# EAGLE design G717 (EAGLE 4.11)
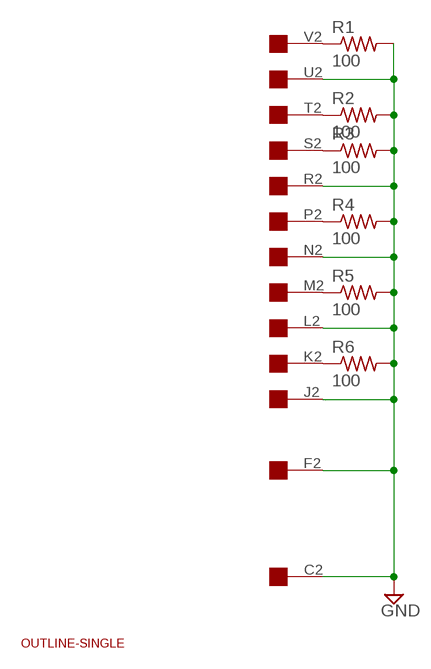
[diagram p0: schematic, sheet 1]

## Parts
R1  100  R-US_0207/10  [0207/10]
R2  100  R-US_0207/10  [0207/10]
R3  100  R-US_0207/10  [0207/10]
R4  100  R-US_0207/10  [0207/10]
R5  100  R-US_0207/10  [0207/10]
R6  100  R-US_0207/10  [0207/10]
U$1  OUTLINE-SINGLE  [SINGLE]
U$3  EDGE-1  [EDGE-CON1]

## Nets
GND [Supply]: R1.2 R2.2 R3.2 R4.2 R5.2 R6.2 U$3.C2 U$3.F2 U$3.J2 U$3.L2 U$3.N2 U$3.R2 U$3.U2
N$1: R1.1 U$3.V2
N$2: R2.1 U$3.T2
N$3: R3.1 U$3.S2
N$4: R4.1 U$3.P2
N$5: R5.1 U$3.M2
N$6: R6.1 U$3.K2
Unconnected: U$3.A2 U$3.B2 U$3.D2 U$3.E2 U$3.H2

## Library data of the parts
R1-R6 = rcl:R-US_: RESISTOR, American symbol
U$1 = dec-con:OUTLINE-*: Board outlines for DEC boards.
U$3 = dec-con:EDGE-1: Single-Sided DEC Edge Connector -- (side 2)

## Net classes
1 Supply: width 0.508 mm, drill 0.508 mm

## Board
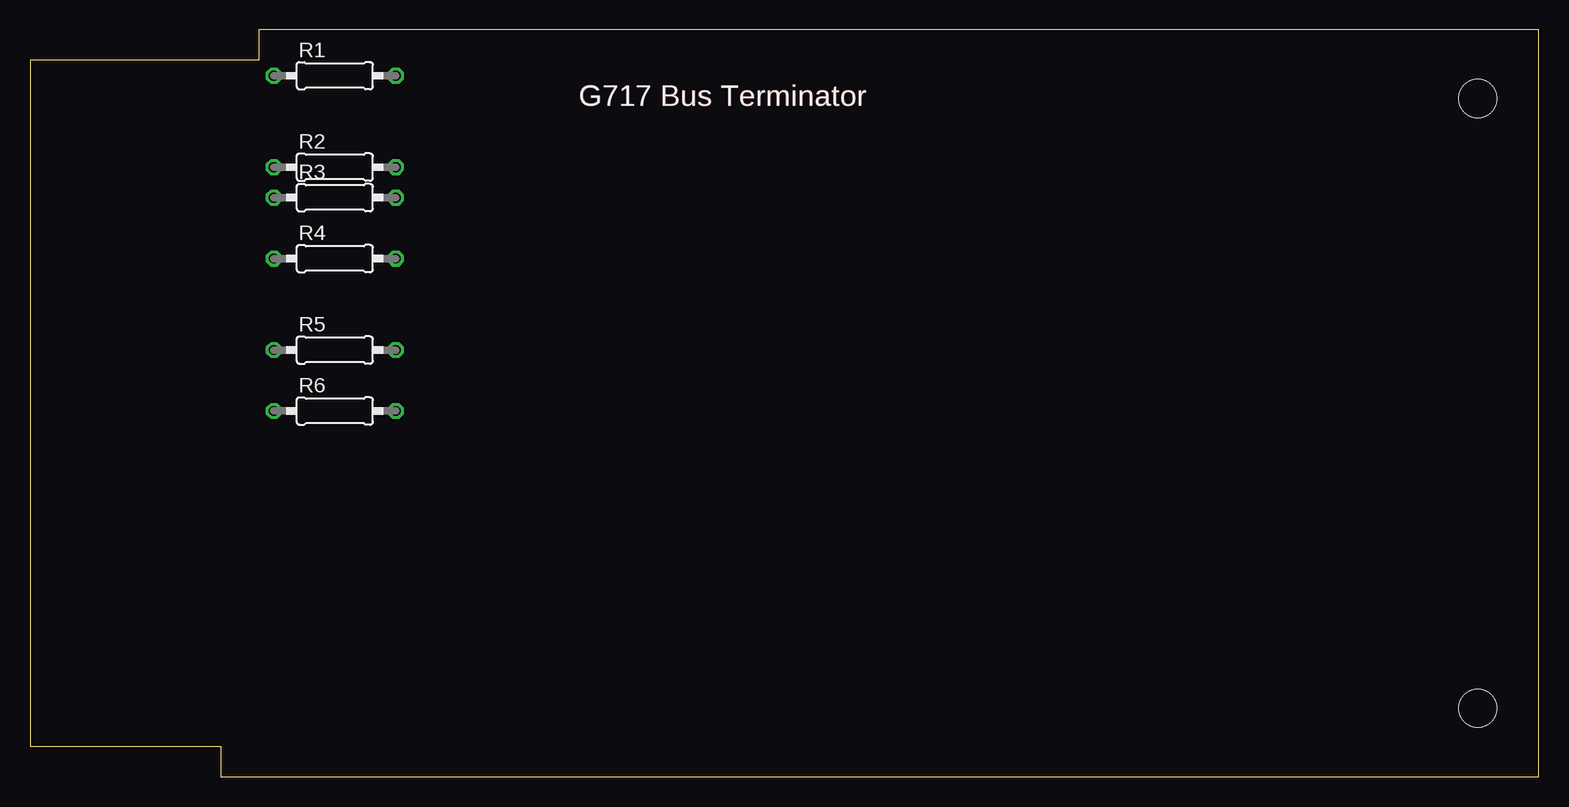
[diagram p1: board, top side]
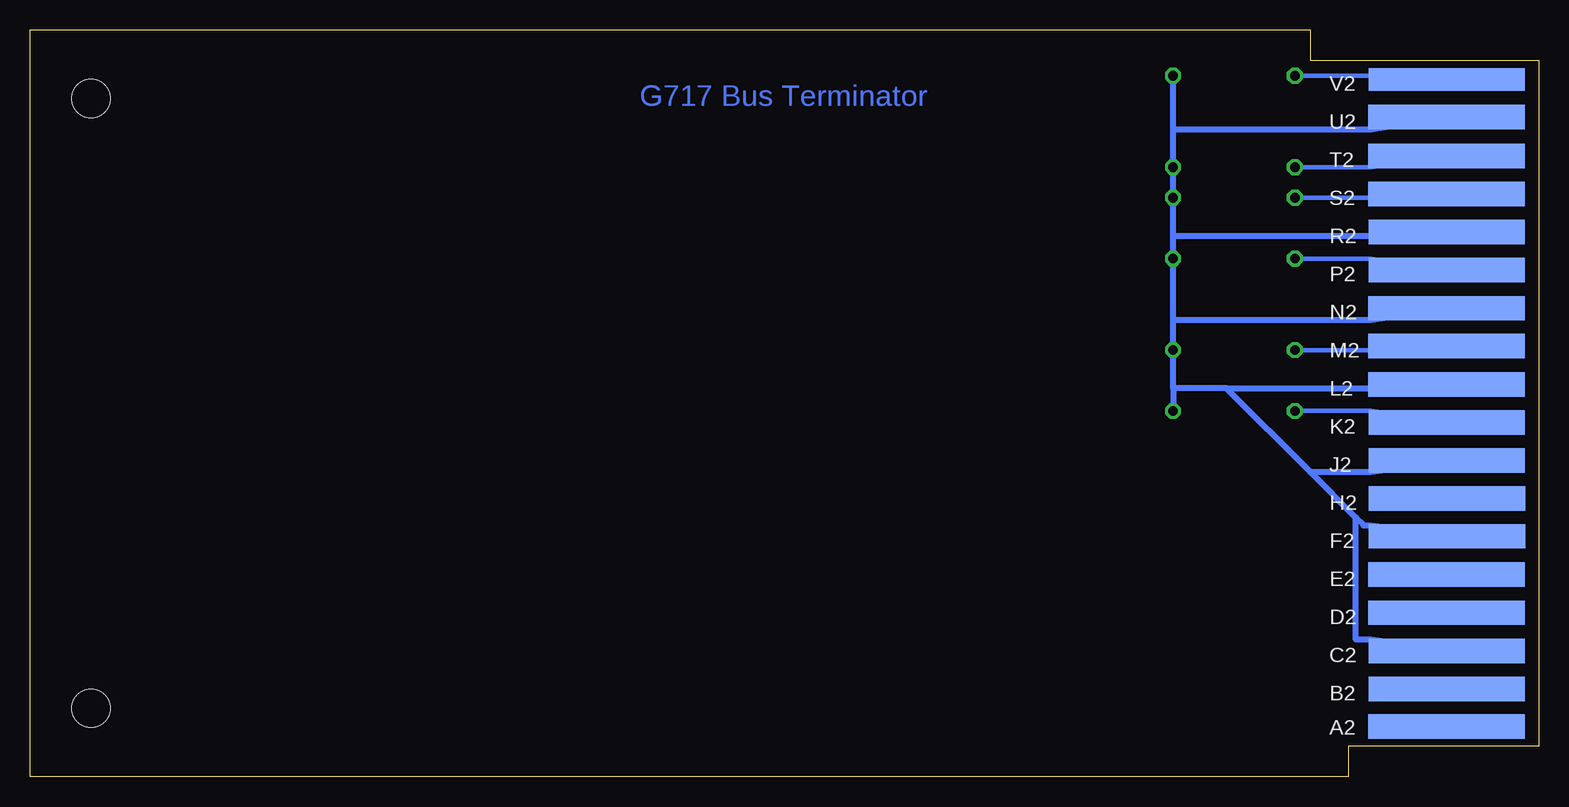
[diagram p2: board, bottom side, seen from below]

Size 125.73 x 62.23 mm. Coordinates in mm from the lower left corner, seen from the top.
Copper layers (1*16): Top 0.035mm / dielectric 1.5mm / Bottom 0.035mm
Design rules "15mils": minimum track width 15mil, minimum drill 24mil, track to track 15mil, track to pad 10mil, pad to pad 10mil, via to via 10mil, smd to smd 10mil, copper to edge 25mil, drill to drill 10mil, minimum pad ring 10mil, minimum via ring 8mil, stop-mask expansion 0mil, vias tented up to drill 0mil, thermal gap 10mil

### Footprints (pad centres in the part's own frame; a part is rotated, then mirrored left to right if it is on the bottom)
0207/10 = drill 0.813 octagon: 1 -5.08,0; 2 5.08,0
SINGLE = hole 3.175: 120.65,56.515; 120.65,5.715
EDGE-CON1 = smd 13.017 x 2.032 bottom: A2 7.69,4.194; B2 7.668,7.328; C2 7.668,10.49; D2 7.693,13.665; E2 7.693,16.84; F2 7.642,20.041; H2 7.642,23.19; J2 7.668,26.34; K2 7.668,29.515; L2 7.693,32.69; M2 7.693,35.89; N2 7.693,39.04; P2 7.668,42.24; R2 7.668,45.39; S2 7.693,48.565; T2 7.693,51.74; U2 7.693,54.966 | smd 13.017 x 1.905 bottom: V2 7.668,58.102

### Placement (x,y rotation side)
R1  25.4,58.42 0 top
R2  25.4,50.8 0 top
R3  25.4,48.26 0 top
R4  25.4,43.18 0 top
R5  25.4,35.56 0 top
R6  25.4,30.48 0 top
U$1  0,0 0 top
U$3  0,0 0 top

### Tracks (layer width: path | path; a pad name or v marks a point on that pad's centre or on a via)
GND
  Bottom 0.508: 30.48,32.38 30.48,34.92 R5.2 30.48,36.2 30.48,38.1 | 30.48,32.38 30.48,31.11 R6.2 | 30.48,45.09 30.48,47.62 R3.2 30.48,48.9 30.48,50.16 R2.2 30.48,51.44 30.48,53.98 | 30.48,45.09 30.48,43.81 R4.2 30.48,42.55 30.48,38.1 | 30.48,53.98 30.48,57.78 R1.2 | 26.04,32.38 13.97,32.38 U$3.L2 | 26.04,32.38 30.48,32.38 | 19.05,25.4 26.04,32.38 | 15.24,21.59 19.05,25.4 | 15.24,21.59 14.61,20.95 13.97,20.95 U$3.F2 | 15.24,21.59 15.24,11.43 13.97,11.43 U$3.C2 | 19.05,25.4 13.97,25.4 U$3.J2 | 30.48,45.09 13.97,45.09 U$3.R2 | 30.48,38.1 13.97,38.1 U$3.N2 | 30.48,53.98 13.97,53.98 U$3.U2
N$1
  Bottom 0.381: R1.1 19.69,58.42 13.97,58.42 U$3.V2
N$2
  Bottom 0.381: R2.1 19.69,50.8 13.97,50.8 U$3.T2
N$3
  Bottom 0.381: R3.1 19.69,48.26 13.97,48.26 U$3.S2
N$4
  Bottom 0.381: R4.1 19.69,43.18 13.97,43.18 U$3.P2
N$5
  Bottom 0.381: R5.1 19.69,35.56 13.97,35.56 U$3.M2
N$6
  Bottom 0.381: R6.1 19.69,30.48 13.97,30.48 U$3.K2

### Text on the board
Top: G717 Bus Terminator
Bottom: G717 Bus Terminator
tNames: G717 Bus Terminator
